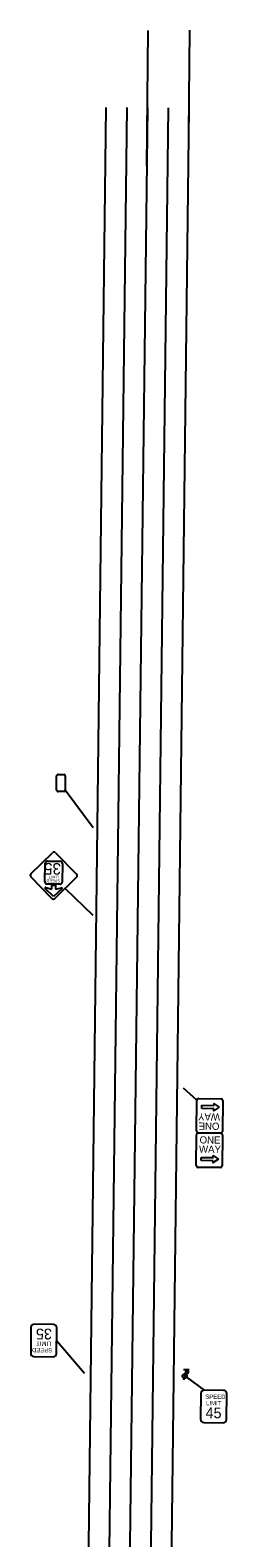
# Model space of a CAD drawing. Extents: x 1652376 to 1652707, y 605933 to 608571.
# Drawn here: x 1652500 to 1652614, y 607695 to 608571 of the extents above; entities that cross this region are included whole.
import ezdxf

# ---------------------------------------------------------------- set-up
doc = ezdxf.new("R2010")
doc.units = 0
for name, color, linetype in [('GE_P_Alignment', 7, 'Continuous'), ('PM_P_CL_Double_Solid', 7, 'Continuous'), ('PV_P_EOP', 7, 'Continuous'), ('RW_P_Fee_RW', 7, 'Continuous'), ('SH_Border', 7, 'Continuous'), ('UT_X_Misc_Cells', 7, 'Continuous')]:
    doc.layers.add(name, color=color, linetype=linetype)

msp = doc.modelspace()

# ---------------------------------------------------------------- linework, layer by layer
at = {"layer": 'GE_P_Alignment'}
for p, q in [((1652590.18, 607792.62), (1652588.57, 607786.62)), ((1652591.78, 607792.62), (1652588.58, 607792.62)), ((1652590.02, 607792.02), (1652590.87, 607792.02)), ((1652589.68, 607790.74), (1652590.87, 607790.74))]:
    msp.add_line(p, q, dxfattribs=at)
for points in [[(1652540.98, 607300.27), (1652543.38, 607498.25), (1652555.8, 608525.74)], [(1652564.99, 607300.89), (1652567.39, 607498.86), (1652579.8, 608525.7)]]:
    msp.add_lwpolyline(points, dxfattribs=at)
msp.add_circle((1652589.21, 607789.02), 1.3, dxfattribs=at)
msp.add_arc((1652590.88, 607791.38), 0.638, 268.8767, 91.1233, dxfattribs=at)
at = {"layer": 'PM_P_CL_Double_Solid'}
for p, q in [((1652528.99, 607301.33), (1652543.79, 608525.88)), ((1652576.99, 607300.75), (1652591.91, 608525.32))]:
    msp.add_line(p, q, dxfattribs=at)
at = {"layer": 'PV_P_EOP'}
msp.add_line((1652552.98, 607300.25), (1652567.79, 608525.6), dxfattribs=at)
at = {"layer": 'RW_P_Fee_RW'}
for p, q in [((1652567.38, 608491.85), (1652568.04, 608570.61)), ((1652591.37, 608491.3), (1652592.25, 608570.75))]:
    msp.add_line(p, q, dxfattribs=at)
at = {"layer": 'SH_Border'}
for p, q in [((1652508.24, 608076.06), (1652508.36, 608086.89)), ((1652509.63, 608088.12), (1652517.13, 608088.04)), ((1652518.36, 608086.78), (1652518.24, 608075.95)), ((1652513.15, 608067.53), (1652508.33, 608072.17)), ((1652508.64, 608072.73), (1652512.11, 608071.87)), ((1652516.98, 608074.71), (1652509.48, 608074.79)), ((1652512.11, 608071.87), (1652512.14, 608074.21)), ((1652512.14, 608074.21), (1652514.31, 608074.18)), ((1652518.07, 608072.06), (1652513.15, 608067.53)), ((1652514.31, 608074.18), (1652514.28, 608071.85)), ((1652514.28, 608071.85), (1652517.77, 608072.63)), ((1652597.36, 607950.26), (1652610.36, 607950.12)), ((1652596.15, 607931.27), (1652596.35, 607949.27)), ((1652599.2, 607944.42), (1652599.22, 607946.3)), ((1652606.29, 607944.35), (1652599.2, 607944.42)), ((1652599.22, 607946.3), (1652606.32, 607946.22)), ((1652606, 607943.51), (1652606.29, 607944.35)), ((1652606.32, 607946.21), (1652606.11, 607946.85)), ((1652609.24, 607945.18), (1652606.31, 607943.27)), ((1652606.42, 607947.08), (1652609.24, 607945.18)), ((1652611.35, 607949.11), (1652611.15, 607931.11)), ((1652595.93, 607911.28), (1652596.13, 607929.27)), ((1652610.14, 607930.12), (1652597.14, 607930.26)), ((1652597.14, 607930.26), (1652610.14, 607930.12)), ((1652611.13, 607929.11), (1652610.93, 607911.11)), ((1652598.74, 607914.21), (1652598.76, 607916.09)), ((1652598.76, 607916.09), (1652605.86, 607916.01)), ((1652605.86, 607916), (1652605.65, 607916.64)), ((1652608.78, 607914.97), (1652605.85, 607913.06)), ((1652605.96, 607916.88), (1652608.78, 607914.97)), ((1652609.92, 607910.12), (1652596.92, 607910.26)), ((1652605.82, 607914.14), (1652598.74, 607914.21)), ((1652605.54, 607913.3), (1652605.82, 607914.14))]:
    msp.add_line(p, q, dxfattribs=at)
for points in [[(1652515, 608129.33), (1652514.98, 608137.66)], [(1652515.81, 608138.5), (1652519.14, 608138.51)], [(1652519.98, 608137.67), (1652520, 608129.34)], [(1652519.17, 608128.51), (1652515.84, 608128.5)], [(1652500.04, 608080.78), (1652512.55, 608093.02)], [(1652514.31, 608093), (1652526.55, 608080.49)], [(1652512.25, 608066.5), (1652500.02, 608079.01)], [(1652526.53, 608078.72), (1652514.02, 608066.48)], [(1652513.25, 607819.03), (1652502.01, 607819.16)], [(1652500.11, 607817.3), (1652499.94, 607802.3)], [(1652514.94, 607802.14), (1652515.11, 607817.14)], [(1652501.8, 607800.41), (1652513.05, 607800.28)], [(1652598.66, 607779), (1652598.5, 607764)], [(1652611.81, 607780.73), (1652600.56, 607780.86)], [(1652613.5, 607763.84), (1652613.66, 607778.84)], [(1652600.35, 607762.11), (1652611.6, 607761.98)]]:
    msp.add_lwpolyline(points, dxfattribs=at)
for centre, radius, start, end in [((1652515.81, 608137.66), 0.833, 90.15158, 180.15158), ((1652519.14, 608137.67), 0.833, 0.15158, 90.15158), ((1652515.83, 608129.33), 0.833, 180.15158, 270.15158), ((1652519.17, 608129.34), 0.833, 270.15158, 0.15158), ((1652513.42, 608092.12), 1.25, 44.3709, 134.3709), ((1652500.91, 608079.89), 1.25, 134.3709, 224.3709), ((1652509.61, 608086.87), 1.25, 89.3709, 179.3709), ((1652517.11, 608086.79), 1.25, 359.3709, 89.3709), ((1652508.56, 608072.41), 0.333, 76.13038, 226.1066), ((1652509.49, 608076.04), 1.25, 179.3709, 269.3709), ((1652516.99, 608075.96), 1.25, 269.3709, 359.3709), ((1652517.85, 608072.3), 0.333, 312.63519, 102.61142), ((1652525.66, 608079.61), 1.25, 314.3709, 44.3709), ((1652513.15, 608067.38), 1.25, 224.3709, 314.3709), ((1652597.35, 607949.26), 1, 89.3709, 179.3709), ((1652610.35, 607949.12), 1, 359.3709, 89.3709), ((1652606.2, 607943.44), 0.208, 161.44751, 303.0964), ((1652606.31, 607946.91), 0.208, 55.79496, 198.43429), ((1652597.13, 607929.26), 1, 89.3709, 179.3709), ((1652597.15, 607931.26), 1, 179.3709, 269.3709), ((1652610.15, 607931.12), 1, 269.3709, 359.3709), ((1652610.13, 607929.12), 1, 359.3709, 89.3709), ((1652605.85, 607916.7), 0.208, 55.79496, 198.43429), ((1652596.93, 607911.26), 1, 179.3709, 269.3709), ((1652605.74, 607913.23), 0.208, 161.44751, 303.0964), ((1652609.93, 607911.12), 1, 269.3709, 359.3709), ((1652501.98, 607817.28), 1.88, 89.3709, 179.3709), ((1652513.23, 607817.16), 1.88, 359.3709, 89.3709), ((1652501.82, 607802.28), 1.88, 179.3709, 269.3709), ((1652513.07, 607802.16), 1.88, 269.3709, 359.3709), ((1652600.54, 607778.98), 1.88, 89.3709, 179.3709), ((1652611.79, 607778.86), 1.88, 359.3709, 89.3709), ((1652600.37, 607763.98), 1.88, 179.3709, 269.3709), ((1652611.62, 607763.86), 1.88, 269.3709, 359.3709)]:
    msp.add_arc(centre, radius, start, end, dxfattribs=at)
at = {"layer": 'UT_X_Misc_Cells'}
for p, q in [((1652536.11, 608107.45), (1652520, 608129.34)), ((1652519.85, 608072.18), (1652536.04, 608056.69)), ((1652596.35, 607949.27), (1652588.64, 607956.19)), ((1652515.03, 607809.59), (1652531.18, 607790.77)), ((1652590.32, 607788.35), (1652600.56, 607780.86))]:
    msp.add_line(p, q, dxfattribs=at)

# ---------------------------------------------------------------- texts
at = {"layer": 'SH_Border'}
for s, height, rotation, p in [('35', 6.667, 179.3709, (1652517.58, 608086.93)), ('SPEED', 1.667, 179.3709, (1652516.97, 608077.49)), ('LIMIT', 1.667, 179.3709, (1652516.25, 608079.72)), ('WAY', 4.172, 179.3709, (1652609.74, 607941.59)), ('ONE', 4.172, 179.3709, (1652609.42, 607936.21)), ('ONE', 4.172, 359.3709, (1652597.85, 607924.18)), ('WAY', 4.172, 359.3709, (1652597.53, 607918.79)), ('35', 6.25, 179.3709, (1652512.3, 607816.54)), ('SPEED', 2.5, 179.3709, (1652512.45, 607805.29)), ('LIMIT', 2.5, 179.3709, (1652511.97, 607809.05)), ('SPEED', 2.5, 359.3709, (1652601.16, 607775.85)), ('LIMIT', 2.5, 359.3709, (1652601.64, 607772.09)), ('45', 6.25, 359.3709, (1652601.3, 607764.6))]:
    msp.add_text(s, height=height, rotation=rotation, dxfattribs=at).set_placement(p)

doc.saveas('drawing.dxf')
